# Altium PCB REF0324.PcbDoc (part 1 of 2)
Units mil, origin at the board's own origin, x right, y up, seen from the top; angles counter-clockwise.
Board outline 2010 x 1686 mil, 4 copper layers (Top Layer, Signal Layer 1, Signal Layer 2, Bottom Layer), stack 61.2 mil thick; 109 components, 70 nets, 426 pads, 300 vias.
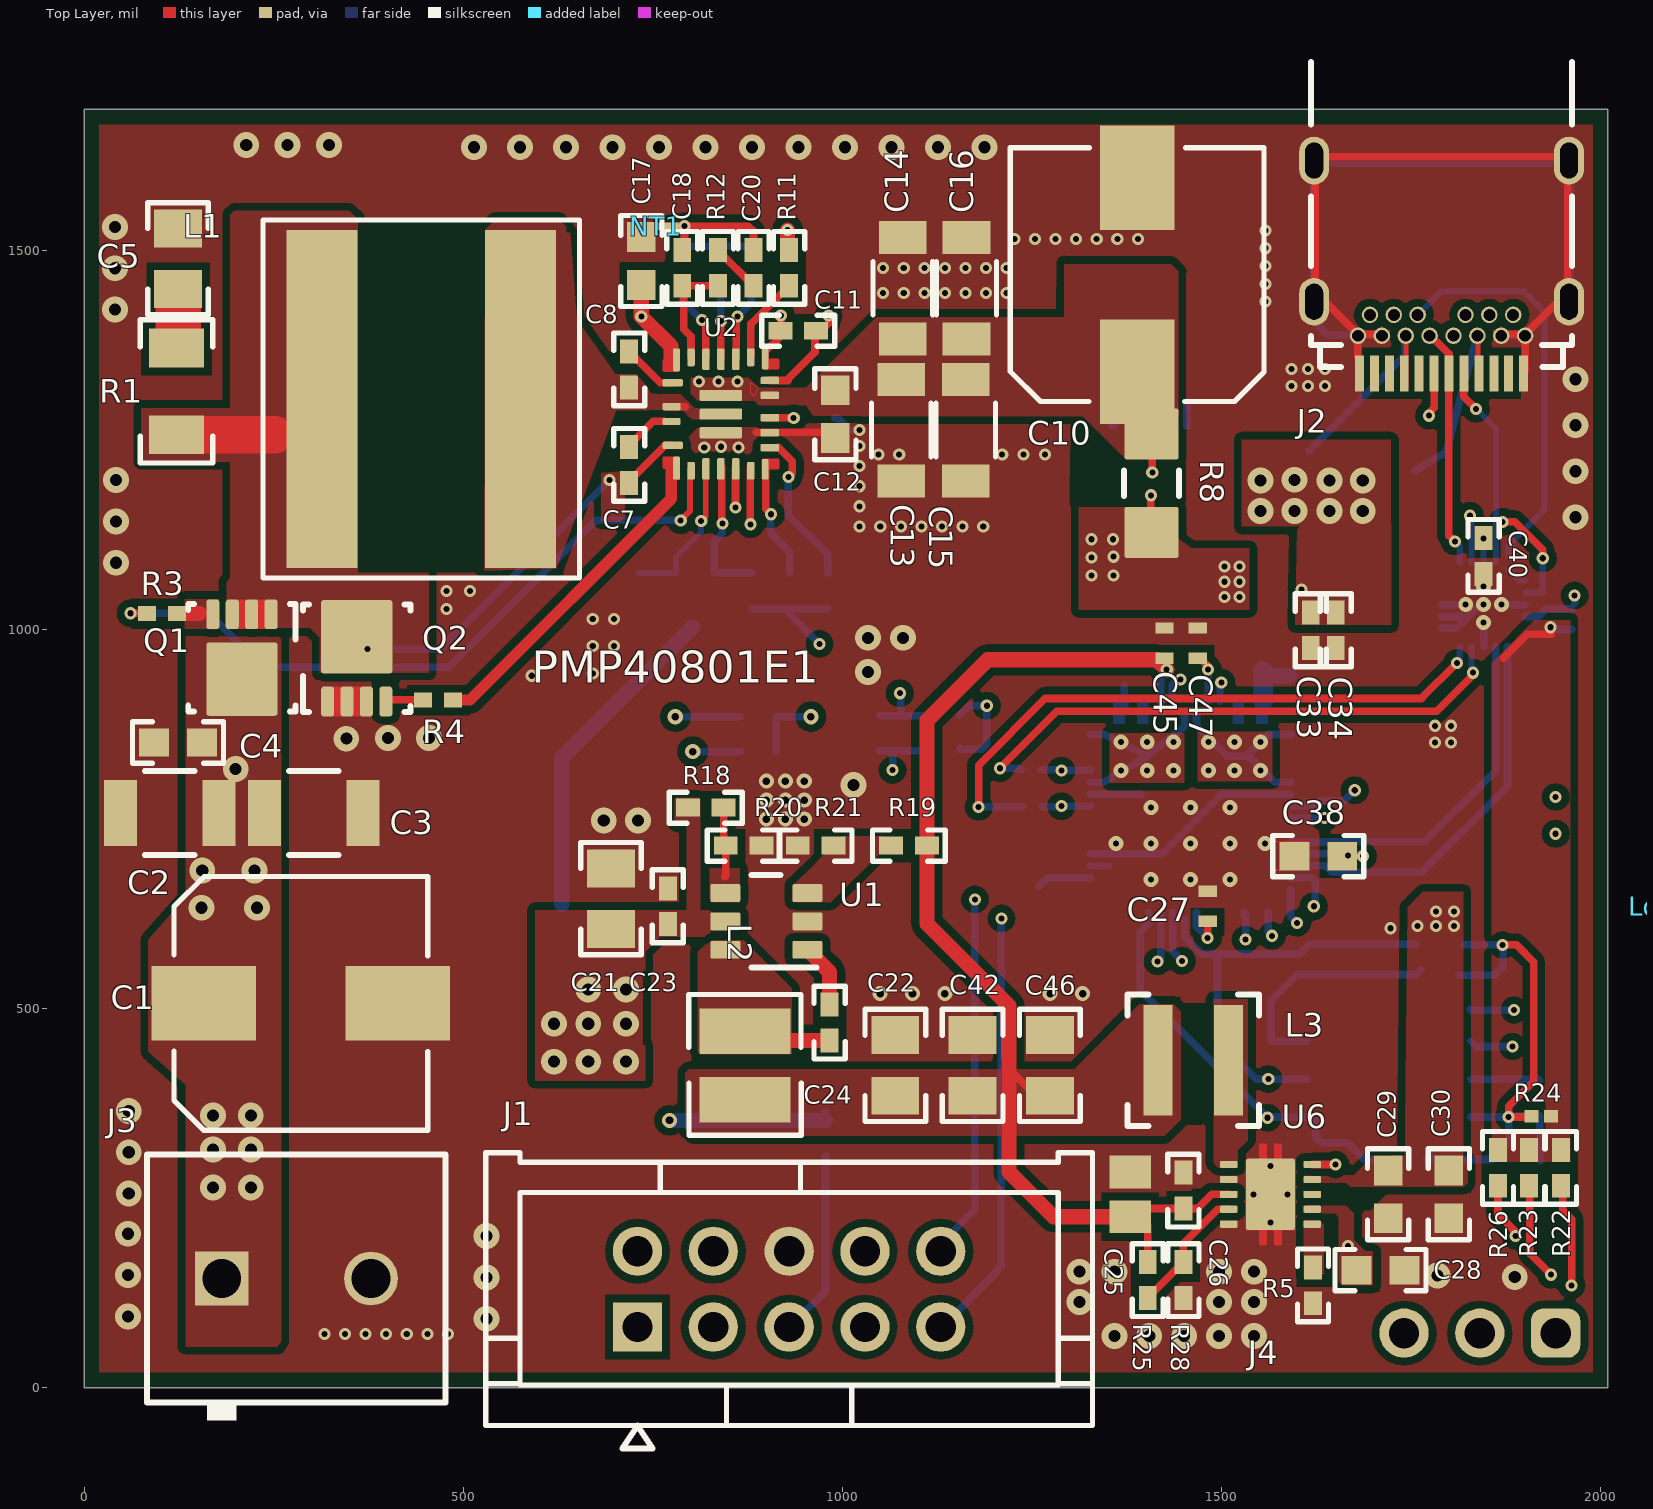
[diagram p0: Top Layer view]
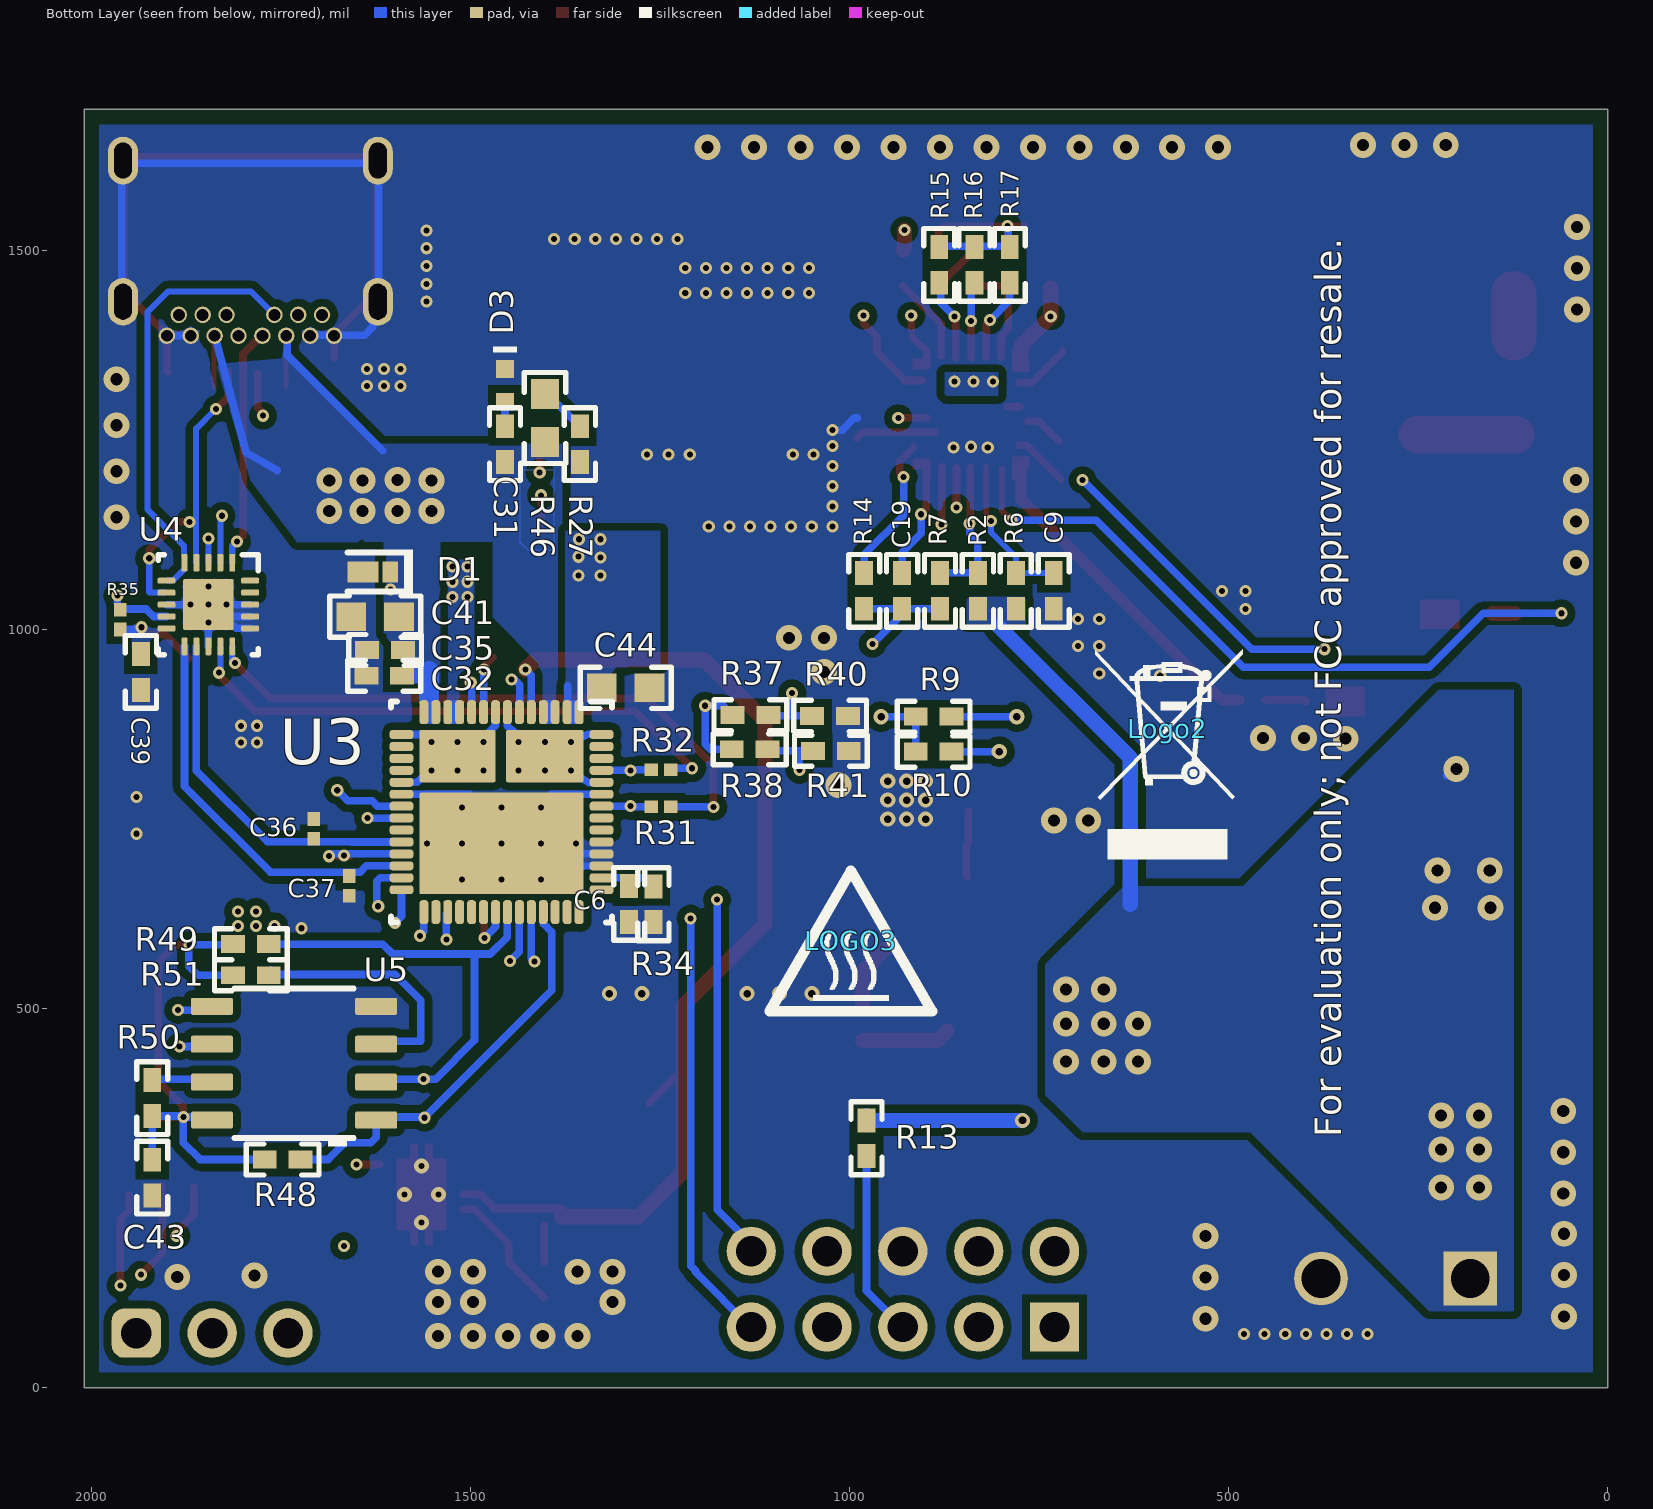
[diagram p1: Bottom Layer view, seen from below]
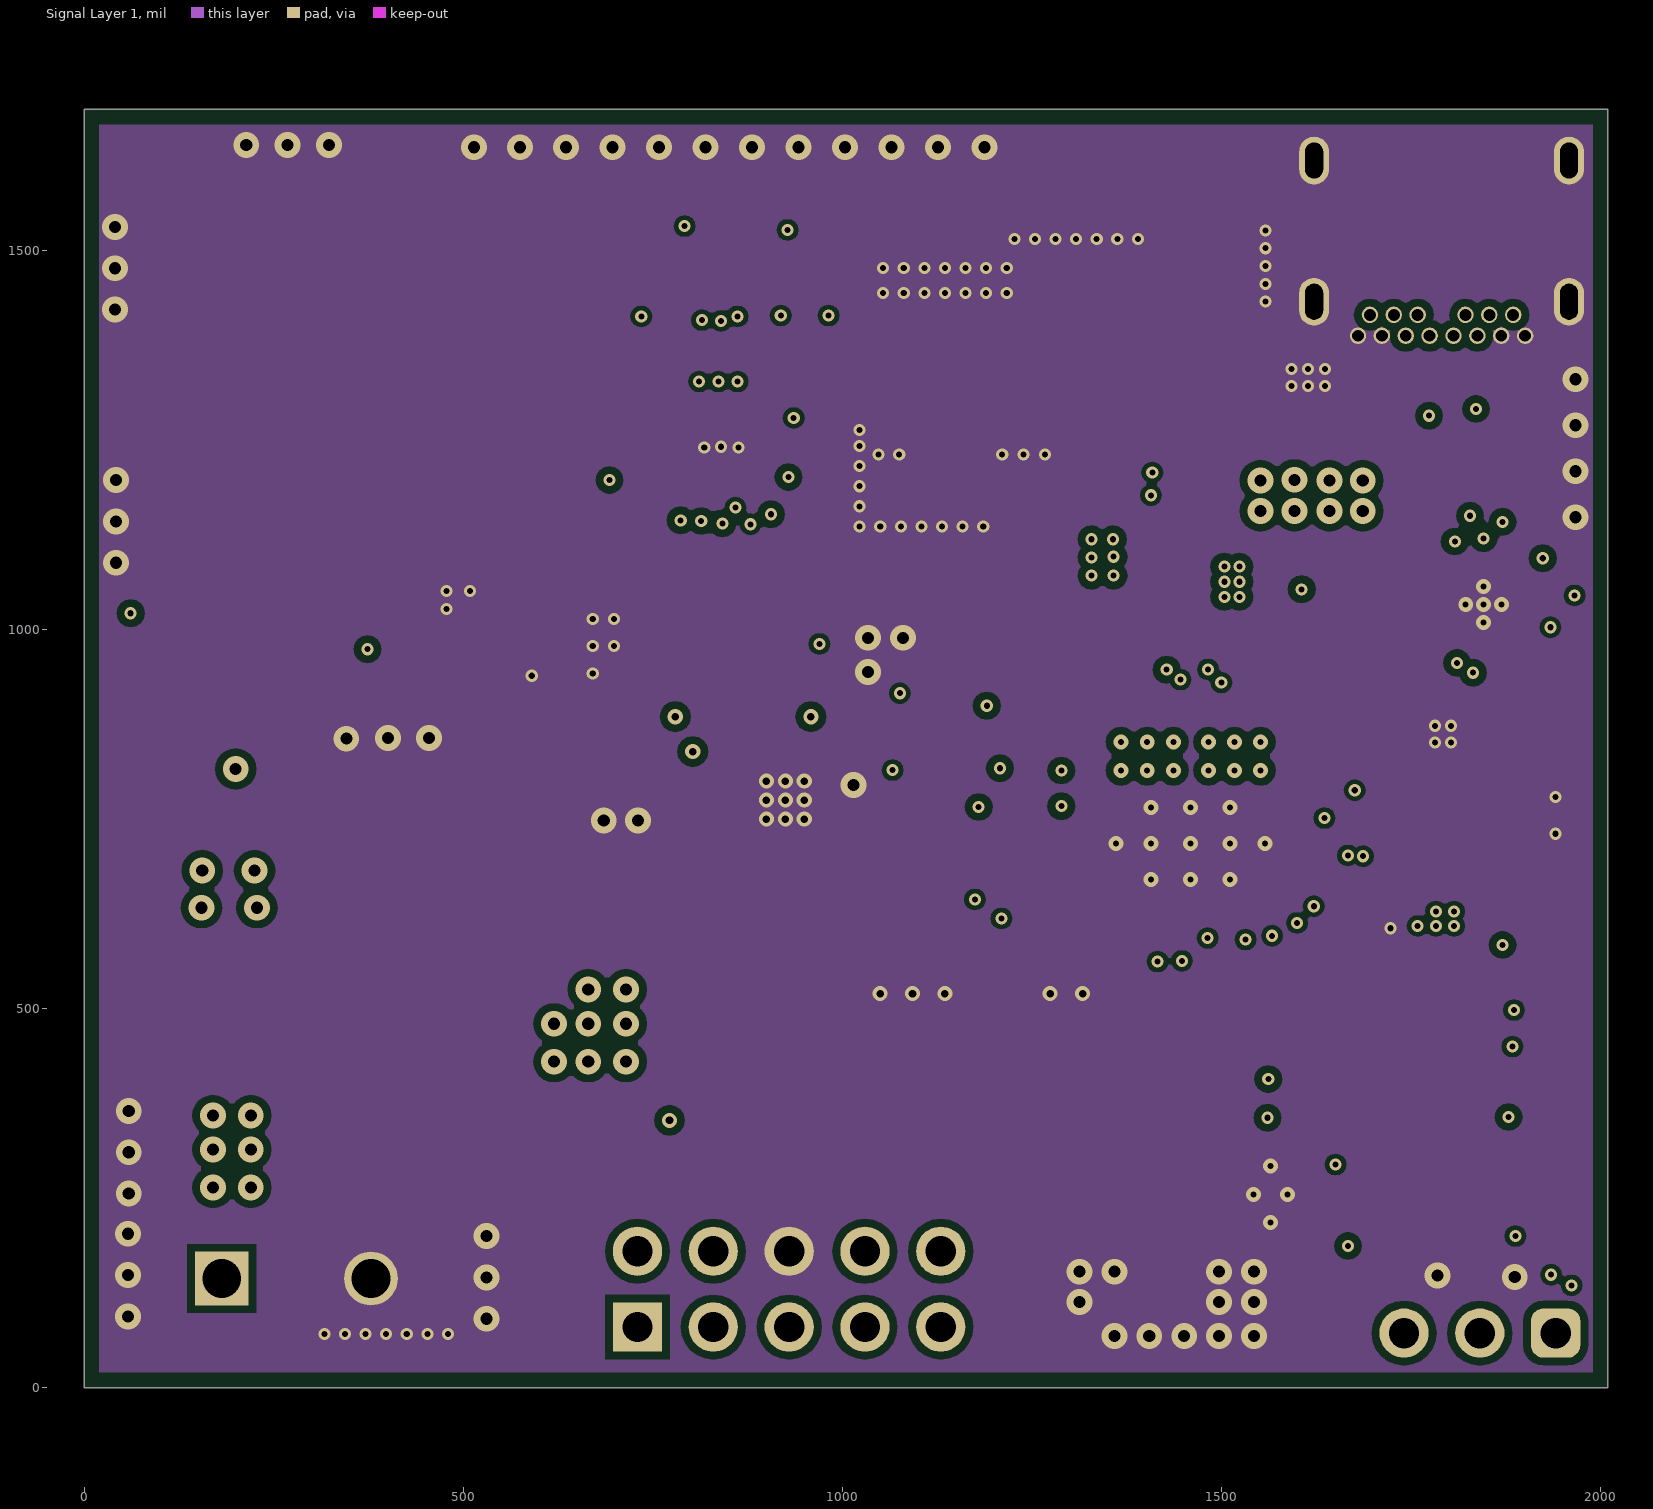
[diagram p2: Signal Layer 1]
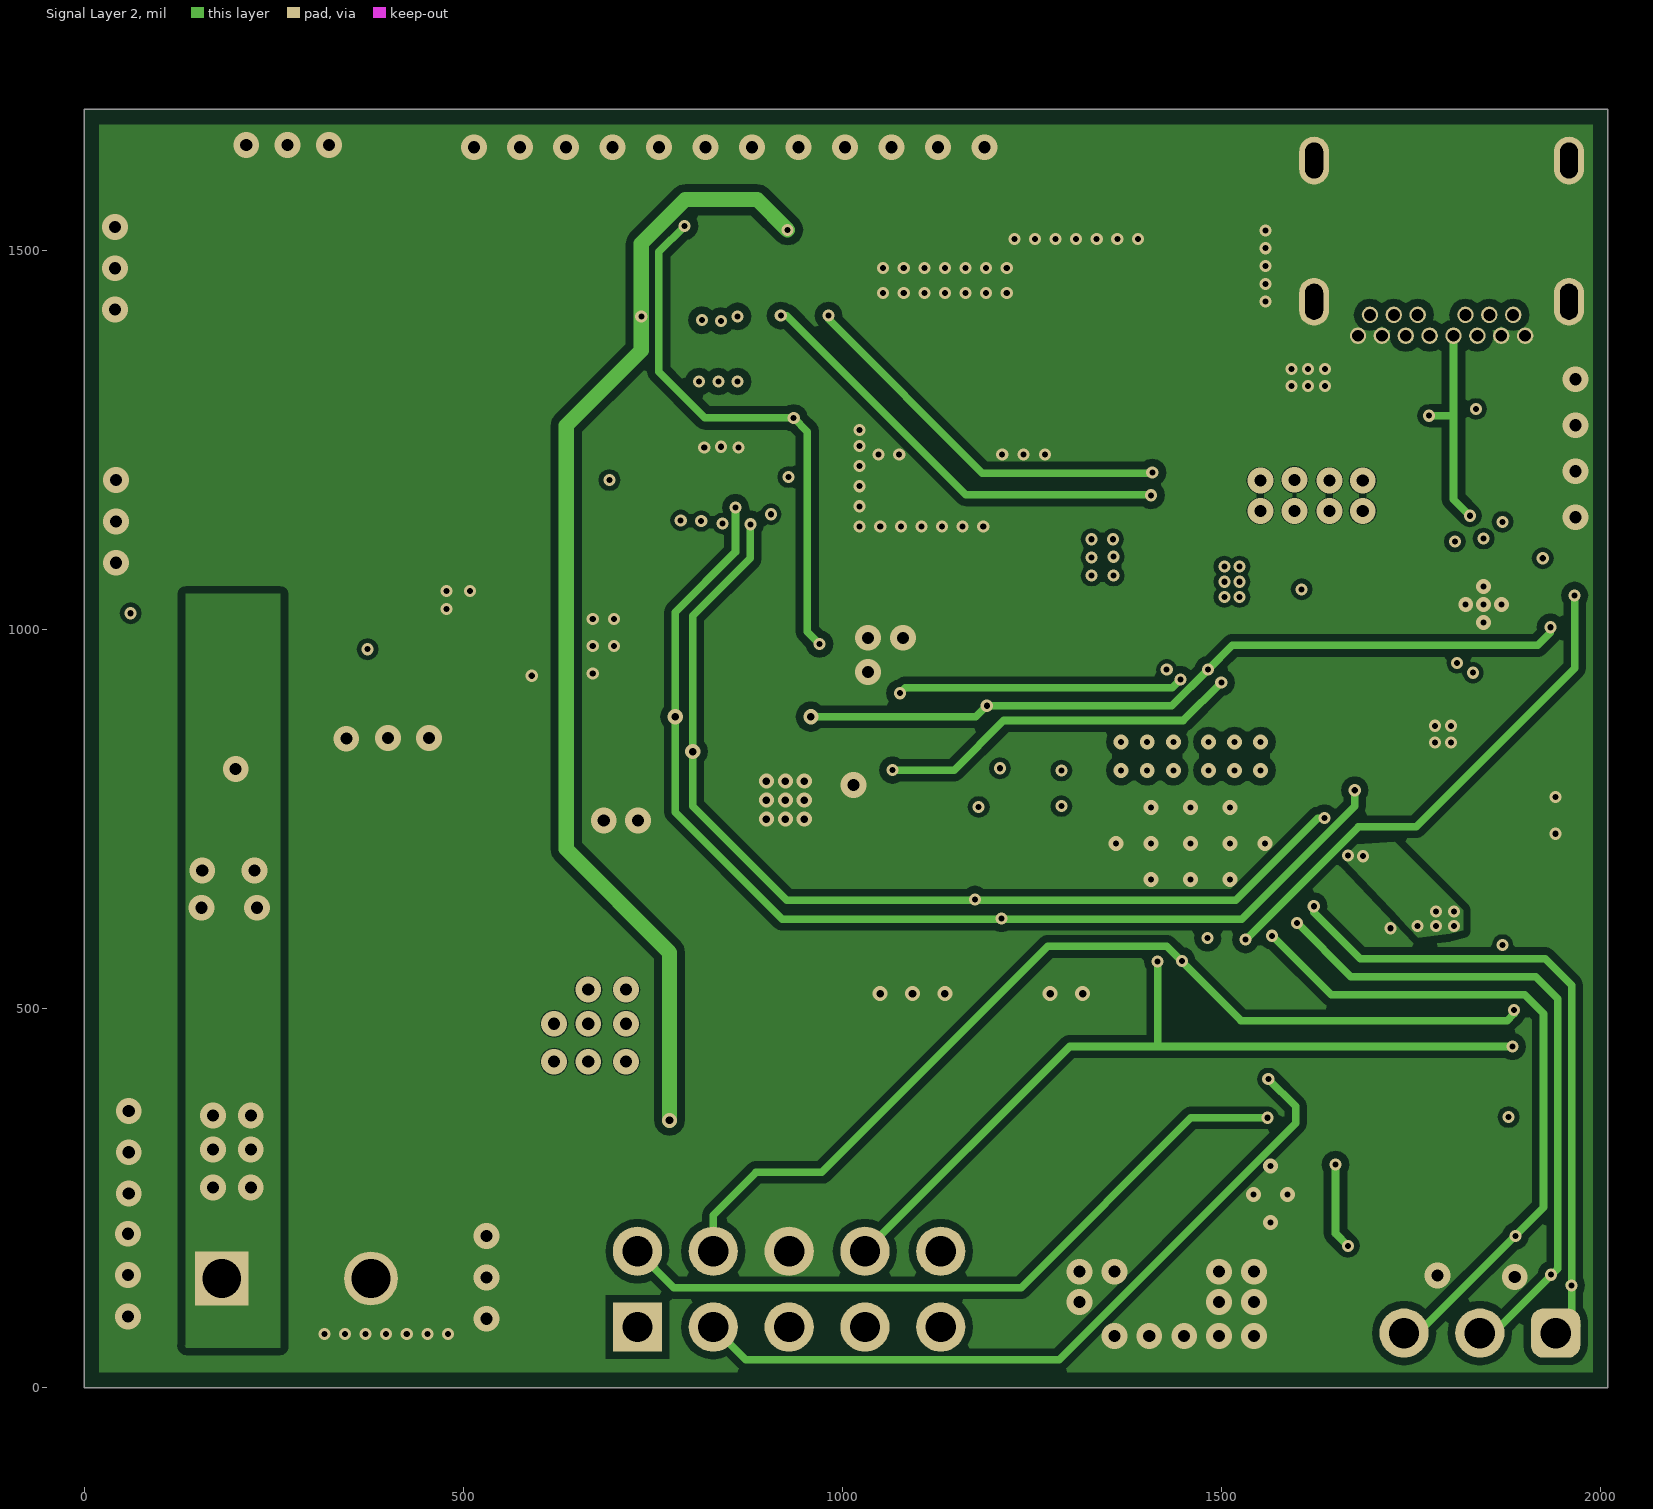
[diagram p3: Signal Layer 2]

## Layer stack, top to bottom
Top Solder: solder mask 0.4, Solder Resist, Dk 3.5
Top Layer: signal copper 2.8
Dielectric 1: core 7, FR-4, Dk 4.2
Signal Layer 1: signal copper 2.8
Dielectric 2: prepreg 36, FR-4, Dk 4.2
Signal Layer 2: signal copper 2.8
Dielectric3: core 7, FR-4, Dk 4.2
Bottom Layer: signal copper 2.8
Bottom Solder: solder mask 0.4, Solder Resist, Dk 3.5

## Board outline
0,0 0,1686 2010,1686 2010,0

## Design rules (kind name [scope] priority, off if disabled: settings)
AcuteAngle [All] p1: minimum=4.50000000000000E+0001 checktracksonly=FALSE
AssemblyTestPointUsage [All] p1: valid=2
BoardOutlineClearance BoardOutlineClearance_1 [ispad and InComponent('J3')] p1: gap=20 ignorepadtopadclearanceinfootprint=FALSE
BoardOutlineClearance BoardOutlineClearance_MountingHoles [OnCopper and InComponentClass('Mounting Holes')] p2: gap=20 ignorepadtopadclearanceinfootprint=FALSE
BoardOutlineClearance BoardOutlineClearance_Poly [OnCopper and IsPoly] p3: gap=20 ignorepadtopadclearanceinfootprint=FALSE
BoardOutlineClearance [OnCopper and Not InComponentClass('Logo') and not InComponentClass('FiducialMark') and not InRegion(1000,500,4000,800) and not InPoly] p4: gap=20 ignorepadtopadclearanceinfootprint=FALSE
Clearance Clearance_3 [InComponent('NT1')] p1: gap=3 ignorepadtopadclearanceinfootprint=FALSE
Clearance Clearance_2 [isPad or IsArc vs IsKeepOut] p2: gap=10 ignorepadtopadclearanceinfootprint=FALSE
Clearance Clearance_1 [InPolygon AND (INNet(VIN) OR InNet('SW')OR InNet('SENS')OR InNet('VBUS1')OR InNet('VBUS2'))] p3: gap=10 ignorepadtopadclearanceinfootprint=FALSE
Clearance Clearance_Keepouts [((IsTrack Or IsArc) And Not InPoly) And IsFree and IsKeepOut vs ((IsTrack Or IsArc) And Not InPoly) And IsFree and IsKeepOut] p4: gap=10 ignorepadtopadclearanceinfootprint=FALSE
Clearance Clearance_Poly [InPolygon] p5: gap=10 ignorepadtopadclearanceinfootprint=FALSE
Clearance [All] p6: gap=3 ignorepadtopadclearanceinfootprint=FALSE
ComponentClearance ComponentClearance_1 [InComponent('U1') vs InComponent('NT1')] p1: gap=0 collisioncheckmode=3 verticalgap=0 showdistances=FALSE
ComponentClearance ComponentClearance_MountingHoles_FiducialMarks [InComponentClass('Mounting Holes') vs InComponentClass('FiducialMark')] p2: gap=50 collisioncheckmode=3 verticalgap=10 showdistances=FALSE
ComponentClearance ComponentClearance_Shunt [InComponentClass('Header') vs InComponentClass('Shunt')] p3: gap=0 collisioncheckmode=3 verticalgap=0 showdistances=FALSE
ComponentClearance ComponentClearance_Logo [InComponentClass('Logo')] p4: gap=50 collisioncheckmode=3 verticalgap=10 showdistances=FALSE
ComponentClearance ComponentClearance_ScrewToNut [(HasFootprint('NY PMS 440 0025 PH')) vs (HasFootprint('Keystone_1902C'))] p5: gap=5 collisioncheckmode=3 verticalgap=10 showdistances=FALSE
ComponentClearance ComponentClearance_MountingHoles [InComponentClass('Mounting Holes')] p6: gap=250 collisioncheckmode=3 verticalgap=100000 showdistances=FALSE
ComponentClearance ComponentClearance_SmallPassives [HasFootprint('0201*') or HasFootprint('0402*') or HasFootprint('0508') or HasFootprint('0603*') or HasFootprint('0612') or HasFootprint('0805*') or HasFootprint('0815*') or HasFootprint('0830*') or HasFootprint('1206*') or HasFootprint('1210*') or HasFootprint('1808*') or HasFootprint('1812*') or HasFootprint('1825*') or HasFootprint('2010*') or HasFootprint('2220*') or HasFootprint('2225*') or HasFootprint('2512*') or HasFootprint('2728*') or HasFootprint('3518*') vs HasFootprint('0201*') or HasFootprint('0402*') or HasFootprint('0508') or HasFootprint('0603*') or HasFootprint('0612') or HasFootprint('0805*') or HasFootprint('0815*') or HasFootprint('0830*') or HasFootprint('1206*') or HasFootprint('1210*') or HasFootprint('1808*') or HasFootprint('1812*') or HasFootprint('1825*') or HasFootprint('2010*') or HasFootprint('2220*') or HasFootprint('2225*') or HasFootprint('2512*') or HasFootprint('2728*') or HasFootprint('3518*')] p7: gap=14.96 collisioncheckmode=3 verticalgap=10 showdistances=FALSE
ComponentClearance ComponentClearance_THtoSMT [IsThruComponent vs IsSMTComponent] p8: gap=30 collisioncheckmode=3 verticalgap=30 showdistances=FALSE
ComponentClearance ComponentClearance_THtoTH [IsThruComponent vs IsThruComponent] p9: gap=30 collisioncheckmode=3 verticalgap=30 showdistances=FALSE
ComponentClearance [All] p10 off: gap=30 collisioncheckmode=3 verticalgap=10 showdistances=FALSE
DiffPairsRouting [InDifferentialPairClass('All Differential Pairs')] p1: maxlimit=10 minlimit=5 mostfreqgap=8 toplayer_minwidth=5 toplayer_maxwidth=10 toplayer_prefwidth=8 midlayer1_minwidth=5 midlayer1_maxwidth=10 midlayer1_prefwidth=8 midlayer2_minwidth=5 midlayer2_maxwidth=10 midlayer2_prefwidth=8 bottomlayer_minwidth=5 bottomlayer_maxwidth=10 bottomlayer_prefwidth=8 maxuncoupledlength=10000
FabricationTestPointUsage TestPointUsage [All] p1: valid=2 allowmultiple=FALSE
FabricationTestpoint Testpoint [All] p1: side=3 testpointundercomponent=TRUE minsize=40 maxsize=100 preferedsize=60 minholesize=0 maxholesize=40 preferedholesize=32 testpointgrid=1 allowsidetop=TRUE allowsidebottom=TRUE usegrid=TRUE gridtolerance=0.01
FanoutControl Fanout_LCC [IsLCC] p1: bgadir=Out bgaviamode=Centered fanoutstyle=Auto fanoutdirection=Alternating viagrid=1 // Fanout_LCC (Default Rule)
FanoutControl Fanout_BGA [IsBGA] p2: bgadir=Out bgaviamode=Centered fanoutstyle=Auto fanoutdirection=Alternating viagrid=1 // Fanout_BGA (Default Rule)
FanoutControl Fanout_Default [All] p4: bgadir=Out bgaviamode=Centered fanoutstyle=Auto fanoutdirection=Alternating viagrid=1 // Fanout_Default (Default Rule)
FanoutControl Fanout_Small [(CompPinCount < 5)] p5: bgadir=Out bgaviamode=Centered fanoutstyle=Auto fanoutdirection=OutThenIn viagrid=1 // Fanout_Small (Default Rule)
HoleSize [All] p1: absolutevalues=TRUE maxlimit=251 minlimit=6 maxpercent=80.000 minpercent=20.000
HoleToHoleClearance [All] p1: gap=6 allowstackedmicrovias=TRUE
MinimumAnnularRing MinimumAnnularRing_ThermalPadVias [IsPad] p1: minimumring=2
MinimumAnnularRing [All] p2: minimumring=3
MinimumSolderMaskSliver MinimumSolderMaskSliver_Logo [InComponentClass('Logo') vs InComponentClass('Logo')] p1: minsoldermaskwidth=1
MinimumSolderMaskSliver [All] p2: minsoldermaskwidth=0
PlaneConnect [All] p1: planeconnectstyle=Direct reliefexpansion=10 reliefentries=4 reliefconductorwidth=10 reliefairgap=10
PolygonConnect [All] p1: connectstyle=Direct reliefconductorwidth=10 reliefentries=4 polygonreliefangle="90 Angle" airgapwidth=10
RoutingVias ThermalPadVias [IsVia and InAnyComponent] p1: holewidth=7.87 width=19.68 viastyle="Through Hole" minholewidth=7.8 minwidth=16 maxholewidth=12.99 maxwidth=23.62
RoutingVias [All] p2: holewidth=16 width=34 viastyle="Through Hole" minholewidth=6 minwidth=10 maxholewidth=40 maxwidth=65
ShortCircuit ShortCircuit_1 [ispad and InComponent('U1')] p1: allowed=TRUE
ShortCircuit [All] p2: allowed=FALSE
SilkToSilkClearance SilkToSilkClearance_Pb-FreeLogo [(HasFootprint('Pb-Free_Overlay_Medium') OR HasFootprint('Pb-Free_Overlay_Small')) vs (HasFootprint('Pb-Free_Overlay_Medium') OR HasFootprint('Pb-Free_Overlay_Small'))] p1: silktosilkclearance=0
SilkToSilkClearance [All] p2: silktosilkclearance=0
SilkToSolderMaskClearance [IsPad] p1: minsilkscreentomaskgap=0 clearancetoexposedcopper=TRUE
SilkToSolderMaskClearance SilkToComponentPadClearance [(IsPad or IsFill or IsRegion) and InAnycomponent] p2: minsilkscreentomaskgap=0 clearancetoexposedcopper=TRUE
SolderMaskExpansion [All] p1: expansion=1.97
Width [All] p1: maxlimit=100 minlimit=6 preferedwidth=10 midlayer1_minwidth=7 midlayer2_minwidth=7 bottomlayer_minwidth=7 minimp=50.000000 maximp=50.000000 favimp=50.000000 checkconnectedcopper=TRUE
14 further rules are at their usual default settings.

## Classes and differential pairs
component class Sheet2_PD_Sch: C6 C27 C31 C32 C33 C34 C35 C36 C37 C38 C39 C40 C41 C43 C44 C45 C47 D1 D3 J2 J4 R22 R23 R24 R26 R27 R31 R32 R34 R35 R37 R38 R40 R41 R46 R48 R49 R50 R51 R? U3 U4 U5
component class Sheet1_Power_Sch: C1 C2 C3 C4 C5 C7 C8 C9 C10 C11 C12 C13 C14 C15 C16 C17 C18 C19 C20 C21 C22 C23 C24 C25 C26 C28 C29 C30 C42 C46 J1 J3 L1 L2 L3 Logo1 Logo2 LOGO3 NT1 Q1 Q2 R1 R2 R3 R4 R5 R6 R7 R8 R9 R10 R11 R12 R13 R14 R15 R16 R17 R18 R19 R20 R21 R25 R28 U1 U2 U6
component class Header: J4

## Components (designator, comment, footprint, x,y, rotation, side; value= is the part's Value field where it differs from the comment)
C1 "EEHZA1H680P" SM_RADIAL_8MM 286,507 r0 top value=68uF
C2 "CGA6P1X7R1N106M250AC" 1210_280 113,758 r180 top value=10uF
C3 "CGA6P1X7R1N106M250AC" 1210_280 303,758 r0 top value=10uF
C4 "GRT188R61H105ME13D" 0603 124,851 r180 top value=1uF
C5 "GRM21AR72E222KW01D" 0805_HV 124,1489 r90 top value=2200pF
C6 "GCM155R71H103KA55D" 0402#1 1291,638 r270 bottom value=0.01uF
C7 "CGA2B3X7R1H104K050BB" 0402#1 719,1217 r270 top value=0.1uF
C8 "CGA2B3X7R1H104K050BB" 0402#1 719,1343 r270 top value=0.1uF
C9 "CGA2B3X7R1H103K050BB" 0402#1 731,1051 r270 bottom value=1uF
C10 "EEHZA1E221P" SM_RADIAL_8MM 1389,1468 r90 top value=220uF
C11 "CGA2B3X7R1H104K050BB" 0402#1 942,1394 r180 top value=0.1uF
C12 "GRT188R61H105ME13D" 0603 991,1284 r270 top value=1uF
C13 "CGA5L1X7R1H106K160AC" 1206_190 1078,1263 r270 top value=10uF
C14 "CGA5L1X7R1H106K160AC" 1206_190 1080,1450 r90 top value=10uF
C15 "CGA5L1X7R1H106K160AC" 1206_190 1163,1263 r270 top value=10uF
C16 "CGA5L1X7R1H106K160AC" 1206_190 1164,1450 r90 top value=10uF
C17 "GRT188R61C475KE13D" 0603 735,1486 r90 top value=4.7uF
C18 "CGA2B2C0G1H101J050BA" 0402#1 789,1477 r90 top value=100pF
C19 "CGA2B3X7R1H103K050BB" 0402#1 931,1051 r270 bottom value=0.01uF
C20 "CGA2B2X7R1H472K050BA" 0402#1 883,1477 r90 top value=4700pF
C21 "C2012X7R1V475K125AC" 0805_HV 695,645 r90 top value=4.7uF
C22 "GRM21BD70J226ME44L" 0805_HV 1070,425 r90 top value=22uF
C23 "GCM155R71H104KE02D" 0402#1 770,635 r90 top value=0.1uF
C24 "GCM155R71H104KE02D" 0402#1 983.37,481.64 r270 top value=0.1uF
C25 "GRM21BR60J476ME15L" 0805L 1380,255 r90 top value=47uF
C26 "GCM155R71H104KE02D" 0402#1 1450,260 r90 top value=0.1uF
C27 "CL05A106MP5NUNC" 0402_070 1482,635 r90 top value=10uF
C28 "C1608X5R1A226M080AC" 0603 1710,155 r0 top value=22uF
C29 "C1608X5R1A226M080AC" 0603 1720,255 r270 top value=22uF
C30 "C1608X5R1A226M080AC" 0603 1800,255 r270 top value=22uF
C31 "GRM188R6YA475KE15D" 0603 1402,1279 r90 bottom value=4.7uF
C32 "GCM155R71H103KA55D" 0402#1 1614,939 r0 bottom value=0.01uF
C33 "GCM155R71H103KA55D" 0402#1 1618,999 r270 top value=0.01uF
C34 "GCM155R71H103KA55D" 0402#1 1651,999 r270 top value=0.01uF
C35 "GCM155R71H103KA55D" 0402#1 1613,973 r0 bottom value=0.01uF
C36 "GRM033R71E221KA01D" 0201 1707,737 r90 bottom value=220pF
C37 "GRM033R71E221KA01D" 0201 1660,662 r270 bottom value=220pF
C38 "C1608X5R1A226M080AC" 0603 1628,701 r180 top value=22uF
C39 "EMK105BJ105KVHF" 0402#1 1935,944 r270 bottom value=1uF
C40 "GCM155R71H104KE02D" 0402#1 1846,1097 r270 top value=0.1uF
C41 "GRM188R61E106MA73D" 0603 1626,1017 r0 bottom value=10uF
C42 "GRM21BD70J226ME44L" 0805_HV 1171.97,425 r90 top value=22uF
C43 "885012205037" 0402#1 1920,277 r270 bottom value=0.1uF
C44 "GRM188R61E106MA73D" 0603 1295.62,923.02 r180 bottom value=10uF
C45 "CL05A106MP5NUNC" 0402_070 1469,982 r90 top value=10uF
C46 "GRM21BD70J226ME44L" 0805_HV 1273.94,425 r90 top value=22uF
C47 "CL05A106MP5NUNC" 0402_070 1425,982 r90 top value=10uF
D1 "NSR20F30NXT5G" DSN2_0603 1631.2,1076 r0 bottom value=30V
D3 "LW QH8G-Q2S2-3K5L-1" "LW QH8G_White" 1455,1322 r90 bottom value=White
J1 "5103308-1" CONN_5103308-1 930,130 r0 top
J2 "632723300011" Wurth_632_723_300_011 1790.5,1754.37 r180 top
J3 "691213710002" Wurth_691213710002 280,144 r0 top
J4 "TSW-103-07-G-S" TSW-103-07-G-S 1841,72 r180 top
L1 "XAL1010-472MEB" XAL1010 445,1304 r0 top value=4.7uH
L2 "ME3220-682MLB" ME3220 871.92,425 r270 top value=6.8uH
L3 "78438356022" WE-MAIA_4020 1463,432 r0 top value=2.2uH
Logo1 "FCC disclaimer" FCC_disclaimer 2090,635 r90 top
Logo2 "WEEE logo" WEEE_Minimum 580.9,869.25 r180 bottom
LOGO3 "CAUTION HOT SURFACE" IEC_HotSurface_Small 998.5,589.62 r180 bottom
NT1 "Net-Tie" Net-Tie_10milWide_30milLong 754,1532 r0 top net-tie
Q1 "IPZ40N04S5L4R8ATMA1" PG-TSDSON-8-32 208.33,962.97 r270 top value=40V
Q2 "IPZ40N04S5L4R8ATMA1" PG-TSDSON-8-32 359.67,962.03 r90 top value=40V
R1 "ERJ-8RQF2R2V" 1206 122,1314 r270 top value=2.20
R2 "CRCW0402100KFKED" 0402#1 831,1051 r270 bottom value=147k
R3 "CRCW06031R00FKEA" 0402#2 103,1021 r0 top value=1.00
R4 "CRCW06031R00FKEA" 0402#2 467,907 r180 top value=1.00
R5 "CRCW040232K4FKED" 0402#1 1621,135 r90 top value=32.4k
R6 "CRCW04020000Z0ED" 0402#1 781,1051 r270 bottom value=0
R7 "CRCW0402115KFKED" 0402#1 881,1051 r90 bottom value=115k
R8 "CRF1206-FZ-R010ELF" FP-CRF1206-FZ-R010ELF_1206-MFG 1408,1193 r270 top
R9 "CRCW04022K20FKED" 0402#1 889.38,885 r0 bottom value=2.20k
R10 "CRCW04022K20FKED" 0402#1 889.38,839 r0 bottom value=2.20k
R11 "CRCW0402102KFKED" 0402#1 930,1477 r270 top value=102k
R12 "CRCW040256K2FKED" 0402#1 836,1477 r270 top value=56.2k
R13 "CRCW04022K20FKED" 0402#1 978,329 r90 bottom value=2.20k
R14 "CRCW040249K9FKED" 0402#1 981,1051 r90 bottom value=49.9k
R15 "CRCW04026K19FKED" 0402#1 882,1481 r270 bottom value=6.19k
R16 "CRCW0402150KFKED" 0402#1 835.5,1481 r270 bottom value=150k
R17 "CRCW040220K0FKED" 0402#1 789,1481 r270 bottom value=20.0k
R18 "CRCW0402100KFKED" 0402#1 820,765 r180 top value=402k
R19 "CRCW040251K1FKED" 0402#1 1088,715 r0 top value=51.1k
R20 "CRCW0402100KFKED" 0402#1 870,715 r180 top value=133k
R21 "CRCW040222K1FKED" 0402#1 965,715 r0 top value=22.1k
R22 "CRCW04023K83FKED" 0402#1 1948,290 r90 top value=3.83k
R23 "CRCW04023K83FKED" 0402#1 1906,290 r90 top value=3.83k
R24 "CRCW02010000Z0ED" 0201 1922,358 r180 top value=0
R25 "CRCW0402100KFKED" 0402#1 1403,142 r90 top value=220k
R26 "ERJ-2RKF1002X" 0402#1 1865,290 r90 top value=10.0k
R27 "CRCW04023R48FKED" 0402#1 1356,1244.51 r90 bottom value=3.48
R28 "CRCW0402100KFKED" 0402#1 1450,142 r90 top value=100k
R31 "CRCW02010000Z0ED" 0201 1249,766 r0 bottom value=0
R32 "CRCW02010000Z0ED" 0201 1249,815 r0 bottom value=0
R34 "CRCW0402100KFKED" 0402#1 1259,637.62 r90 bottom value=100k
R35 "RC0201JR-7D100KL" 0201 1962,1013 r270 bottom value=100k
R37 "ERJ-2RKF1002X" 0402#1 1131,887 r0 bottom value=10.0k
R38 "ERJ-2RKF1002X" 0402#1 1132,842 r0 bottom value=10.0k
R40 "CRCW0402100KFKED" 0402#1 1026,886 r0 bottom value=100k
R41 "CRCW0402100KFKED" 0402#1 1025,840 r0 bottom value=100k
R46 "ERJ-2RKF1002X" 0402#1 1454.75,1244.51 r270 bottom value=10.0k
R48 "CRCW04023K30JNED" 0402#1 1748,301 r0 bottom value=3.3k
R49 "CRCW04023K30JNED" 0402#1 1790,585 r0 bottom value=3.3k
R50 "CRCW04023K30JNED" 0402#1 1920,382 r270 bottom value=3.3k
R51 "CRCW04023K30JNED" 0402#1 1790,544 r0 bottom value=3.3k
U1 "TPS560430YDBVR" DBV0006A_N 900,615 r180 top
U2 "TPS55288dev" RPM0026A 839.96,1284.16 r90 top
U3 "TPS65987DDHRSHR" RSH0056E 1459.38,759.11 r270 bottom
U4 "TPD6S300ARUKR" RUK0020B 1846,1032.88 r270 bottom
U5 "MX25L8006EM1I-12G" SOP-8_150MIL 1733,428 r0 bottom
U6 "TPS2500DRCR" DRC0010J 1564.88,255 r0 top

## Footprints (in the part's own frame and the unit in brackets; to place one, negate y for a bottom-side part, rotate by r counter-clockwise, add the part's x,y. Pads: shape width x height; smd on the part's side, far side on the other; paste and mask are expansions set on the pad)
0201 [mm] "Data from Kemet datasheet CC101_COM dated 7/28/11"
  rect 0.46x0.42 smd mask+0.048: 1(-0.33,0) 2(0.33,0)
  body extent -0.31,-0.16 0.31,0.16, height 0.26
0402#1 [mm] "0402 from SM-752 data"
  rect 0.8x0.6 smd: 1(-0.6,0) 2(0.6,0)
  silkscreen extent -1.22,-0.52 1.22,0.52, body extent -0.55,-0.3 0.55,0.3, height 0.6
0402#2 [mm] "Chip Capacitor, Body 1.0x0.5mm, IPC High Density"
  rect 0.6x0.5 smd: 1(-0.5,0) 2(0.5,0)
  body extent -0.55,-0.3 0.55,0.3, height 1.3
0402_070 [mil] "SMD, 2-Leads, Body 1.2x0.7mm, Height 0.7mm"
  rect 15x24 smd: 1(-20,0) 2(20,0)
  body extent -24,-14 24,14, height 28
0603 [mm] "0603 from SM-752 data"
  rect 1x0.95 smd: 1(-0.8,0) 2(0.8,0)
  silkscreen extent -1.52,-0.69 1.52,0.69, body extent -0.87,-0.47 0.87,0.47, height 1
0805_HV [mil] "0805 with 30mil clearance between pads"
  rect 50x63 smd: 1(-40,0) 2(40,0)
  silkscreen extent -74,-40 74,40, body extent -43,-29 43,29, height 57
0805L [mm] "0805 from SM-752 data"
  rect 1.1x1.4 smd: 1(-0.75,0) 2(0.75,0)
  body extent -1.1,-0.72 1.1,0.72, height 1.45
1206 [mm] "1206 from SM-752 data"
  rect 1.3x1.85 smd: 1(-1.45,0) 2(1.45,0)
  silkscreen extent -2.4,-1.21 2.4,1.21, body extent -1.7,-0.9 1.7,0.9, height 1.35
1206_190 [mm] "1206_190"
  rect 1.1x1.6 smd: 1(-1.7,0) 2(1.7,0)
  silkscreen extent -0.9,-1 0.9,1, body extent -1.75,-0.95 1.75,0.95, height 1.9
1210_280 [mm] "SMD, 2-Leads, Body 3.6x2.8mm, Height 2.8mm"
  rect 1.1x2.2 smd: 1(-1.65,0) 2(1.65,0)
  silkscreen extent -0.84,-1.4 0.84,1.4, body extent -1.8,-1.4 1.8,1.4, height 2.8
CONN_5103308-1 [mm] "TE Connectivity (AMP) Rev E datasheet"
  rect 1.65x1.65 hole 1.016 mask+0: 1(-5.08,-1.27)
  round 1.65 hole 1.016 mask+0: 2(-5.08,1.27) 3(-2.54,-1.27) 4(-2.54,1.27) 5(0,-1.27) 6(0,1.27) 7(2.54,-1.27) 8(2.54,1.27) 9(5.08,-1.27) 10(5.08,1.27)
  silkscreen extent -10.16,-5.33 10.16,4.57, body extent -10.16,-4.57 10.16,4.57, height 9.87
DBV0006A_N [mm] "SOT23, 6-Leads, Body 2.9x1.6mm, Pitch 0.95mm, Lead Span 2.8mm, IPC Medium Density"
  rrect17% 1x0.6 smd: 1(-1.375,0.95) 2(-1.375,0) 3(-1.375,-0.95) 4(1.375,-0.95) 5(1.375,0) 6(1.375,0.95)
  silkscreen extent -1.67,-1.55 0.5,1.55, body extent -1.42,-1.46 1.42,1.46, height 1.12
DRC0010J [mm] "VSON-10"
  rrect42% 0.6x0.24 smd: 1(-1.4,1) 2(-1.4,0.5) 3(-1.4,0) 4(-1.4,-0.5) 5(-1.4,-1) 6(1.4,-1) 7(1.4,-0.5) 8(1.4,0) 9(1.4,0.5) 10(1.4,1)
  rrect12% 1.65x2.4 smd paste-1 mask-2: 11(0,0)
  Top Layer region: -0.375,-1.65 -0.375,-1.2 -0.775,-1.2 -0.794,-1.196 -0.81,-1.185 -0.821,-1.169 -0.825,-1.15 -0.825,-1.15 -0.825,1.15 -0.821,1.169 -0.81,1.185 -0.794,1.196 -0.775,1.2 -0.775,1.2 -0.375,1.2 -0.375,1.65 -0.371,1.669 -0.36,1.685 -0.344,1.696 -0.325,1.7 -0.325,1.7 -0.325,1.7 -0.175,1.7 -0.175,1.7 -0.156,1.696 -0.14,1.685 -0.129,1.669 -0.125,1.65 -0.125,1.65 -0.125,1.2 0.125,1.2 0.125,1.65 0.129,1.669 0.14,1.685 0.156,1.696 0.175,1.7 0.175,1.7 0.175,1.7 0.325,1.7 0.325,1.7 0.344,1.696 0.36,1.685 0.371,1.669 0.375,1.65 0.375,1.65 0.375,1.2 0.775,1.2 0.794,1.196 0.81,1.185 0.821,1.169 0.825,1.15 0.825,1.15 0.825,-1.15 0.821,-1.169 0.81,-1.185 0.794,-1.196 0.775,-1.2 0.775,-1.2 0.375,-1.2 0.375,-1.65 0.371,-1.669 0.36,-1.685 0.344,-1.696 0.325,-1.7 0.325,-1.7 0.175,-1.7 0.156,-1.696 0.14,-1.685 0.129,-1.669 0.125,-1.65 0.125,-1.65 0.125,-1.2 -0.125,-1.2 -0.125,-1.65 -0.129,-1.669 -0.14,-1.685 -0.156,-1.696 -0.175,-1.7 -0.175,-1.7 -0.325,-1.7 -0.344,-1.696 -0.36,-1.685 -0.371,-1.669 -0.375,-1.65
  body extent -1.5,-1.5 1.5,1.5, height 1
DSN2_0603 [mm] "SMD, 2-Leads, Body 1.6x0.8mm"
  rect 0.52x0.7 smd: 1(-0.64,0)
  rect 1.05x0.7 smd: 2(0.275,0)
  silkscreen extent -1.4,-0.75 0.8,0.75, body extent -0.8,-0.4 0.8,0.4, height 0.31
FCC_disclaimer [mil]
FP-CRF1206-FZ-R010ELF_1206-MFG [mm]
  rrect6% 1.7x1.8 smd paste+0 mask+0: 1(-1.65,0) 2(1.65,0)
  silkscreen extent -0.42,-0.93 0.42,0.93, body extent -2.6,-1.02 2.6,1.02, height 0.25
IEC_HotSurface_Small [mil]
  silkscreen extent -107,-93 107,92
"LW QH8G_White" [mm] "SMD, 2-Leads, Body 1x0.5mm"
  rect 0.6x0.6 smd paste-0.3: 1(-0.55,0) 2(0.55,0)
  silkscreen extent 1.1,-0.4 1.3,0.4, body extent -0.55,-0.3 0.55,0.3, height 0.4
ME3220 [mm] "Coilcraft SMT Power Inductor ME3220 inductors"
  rect 1.52x3.05 smd: 1(-1.145,0) 2(1.145,0)
  silkscreen extent -2.38,-1.88 2.34,1.88, body extent -1.75,-1.41 1.75,1.4
Net-Tie_10milWide_30milLong [mil] "10mil net tie, no solder mask opening, no solder paste"
  rect 30x10 smd paste-5 mask-5: 1(-15,0) 2(15,0)
PG-TSDSON-8-32 [mm] "SMD, 8-Leads, Body 3.3x3.3mm"
  rrect45% 1x0.44 smd paste-1 mask-0.05: 1(-1.45,0.975) 2(-1.45,0.325) 3(-1.45,-0.325) 4(-1.45,-0.975) 5(1.45,-0.975) 6(1.45,-0.325) 7(1.45,0.325) 8(1.45,0.975)
  rrect6% 1.71x2.29 on Top Solder: 9(0.395,0)
  rrect8% 2.46x2.39 smd paste-2 mask-2: 9(0.72,0)
  rrect42% 0.3x0.24 on Top Paste: ""(-1.695,-0.325) ""(-1.695,0.325) ""(-1.695,0.975)
  rrect42% 0.7x0.24 on Top Paste: ""(-1.5,-0.975)
  rrect29% 0.35x0.67 on Top Paste: ""(-1.225,0.76) ""(-1.22,-0.11)
  rrect42% 1.4x0.24 on Top Paste: ""(0.35,0.975) ""(0.35,-0.975)
  rrect9% 1.4x1.09 on Top Paste: ""(0.35,0)
  rrect42% 0.6x0.24 on Top Paste: ""(1.55,0.975) ""(1.55,-0.325) ""(1.55,0.325) ""(1.55,-0.975)
  Top Layer region: -1.95,-0.325 -0.95,-0.325 -0.95,1 -1.95,1
  silkscreen extent -1.8,-1.8 1.8,1.8, body extent -1.7,-1.7 1.7,1.7, height 1.15
RPM0026A [mm] "VQFN-HR-26"
  rrect44% 0.775x0.225 smd: 1(-1.812,1.487) 19(1.812,1.487)
  rrect40% 0.6x0.25 smd: 2(-1.9,1) 6(-1.9,-1) 14(1.9,-1) 18(1.9,1)
  rrect40% 0.725x0.25 smd: 3(-1.837,0.5) 4(-1.837,0) 5(-1.837,-0.5) 15(1.837,-0.5) 16(1.837,0) 17(1.837,0.5)
  rrect44% 0.7x0.225 smd: 7(-1.85,-1.488) 13(1.85,-1.488)
  rrect40% 0.25x0.625 smd: 8(-1.125,-1.637) 9(-0.625,-1.637) 10(-0.125,-1.637) 11(0.625,-1.637) 12(1.125,-1.637)
  rrect40% 0.25x0.675 smd: 20(1.05,1.612) 23(-1.05,1.612)
  rrect40% 0.25x0.6 smd: 21(0.25,1.65) 22(-0.25,1.65)
  rrect27% 0.375x1.425 smd: 24(-0.625,0) 25(0,0) 26(0.625,0)
  Top Layer region: -2.15,-1.6 -2.169,-1.596 -2.185,-1.585 -2.196,-1.569 -2.2,-1.55 -2.2,-1.55 -2.2,-1.425 -2.196,-1.406 -2.185,-1.39 -2.169,-1.379 -2.15,-1.375 -2.15,-1.375 -1.55,-1.375 -1.531,-1.379 -1.515,-1.39 -1.504,-1.406 -1.5,-1.425 -1.5,-1.425 -1.5,-1.9 -1.504,-1.919 -1.515,-1.935 -1.531,-1.946 -1.55,-1.95 -1.55,-1.95 -1.8,-1.95 -1.819,-1.946 -1.835,-1.935 -1.846,-1.919 -1.85,-1.9 -1.85,-1.9 -1.85,-1.6
  Top Layer region: 1.5,-1.9 1.504,-1.919 1.515,-1.935 1.531,-1.946 1.55,-1.95 1.55,-1.95 1.8,-1.95 1.819,-1.946 1.835,-1.935 1.846,-1.919 1.85,-1.9 1.85,-1.9 1.85,-1.6 2.15,-1.6 2.169,-1.596 2.185,-1.585 2.196,-1.569 2.2,-1.55 2.2,-1.55 2.2,-1.425 2.196,-1.406 2.185,-1.39 2.169,-1.379 2.15,-1.375 2.15,-1.375 1.55,-1.375 1.531,-1.379 1.515,-1.39 1.504,-1.406 1.5,-1.425 1.5,-1.425
  Top Layer region: 1.425,1.425 1.429,1.406 1.44,1.39 1.456,1.379 1.475,1.375 1.475,1.375 2.15,1.375 2.169,1.379 2.185,1.39 2.196,1.406 2.2,1.425 2.2,1.425 2.2,1.55 2.196,1.569 2.185,1.585 2.169,1.596 2.15,1.6 2.15,1.6 1.825,1.6 1.825,1.9 1.821,1.919 1.81,1.935 1.794,1.946 1.775,1.95 1.775,1.95 1.475,1.95 1.456,1.946 1.44,1.935 1.429,1.919 1.425,1.9 1.425,1.9
  Top Layer region: -2.15,1.375 -2.169,1.379 -2.185,1.39 -2.196,1.406 -2.2,1.425 -2.2,1.425 -2.2,1.55 -2.193,1.575 -2.175,1.593 -2.15,1.6 -2.15,1.6 -1.825,1.6 -1.825,1.9 -1.821,1.919 -1.81,1.935 -1.794,1.946 -1.775,1.95 -1.775,1.95 -1.475,1.95 -1.456,1.946 -1.44,1.935 -1.429,1.919 -1.425,1.9 -1.425,1.9 -1.425,1.425 -1.429,1.406 -1.44,1.39 -1.456,1.379 -1.475,1.375 -1.475,1.375
  body extent -2,-1.75 2,1.75, height 1
RSH0056E [mm] "SMD, 56-Leads, Body 7x7mm, Pitch 0.4mm"
  rrect67% 0.8x0.3 smd paste-0.05 mask-0.05: 1(-3.35,2.6) 2(-3.35,2.2) 3(-3.35,1.8) 4(-3.35,1.4) 5(-3.35,1) 6(-3.35,0.6) 7(-3.35,0.2) 8(-3.35,-0.2) 9(-3.35,-0.6) 10(-3.35,-1) 11(-3.35,-1.4) 12(-3.35,-1.8) 13(-3.35,-2.2) 14(-3.35,-2.6) 29(3.35,-2.6) 30(3.35,-2.2) 31(3.35,-1.8) 32(3.35,-1.4) 33(3.35,-1) 34(3.35,-0.6) 35(3.35,-0.2) 36(3.35,0.2) 37(3.35,0.6) 38(3.35,1) 39(3.35,1.4) 40(3.35,1.8) 41(3.35,2.2) 42(3.35,2.6)
  rrect67% 0.3x0.8 smd paste-0.05 mask-0.05: 15(-2.6,-3.35) 16(-2.2,-3.35) 17(-1.8,-3.35) 18(-1.4,-3.35) 19(-1,-3.35) 20(-0.6,-3.35) 21(-0.2,-3.35) 22(0.2,-3.35) 23(0.6,-3.35) 24(1,-3.35) 25(1.4,-3.35) 26(1.8,-3.35) 27(2.2,-3.35) 28(2.6,-3.35) 43(2.6,3.35) 44(2.2,3.35) 45(1.8,3.35) 46(1.4,3.35) 47(1,3.35) 48(0.6,3.35) 49(0.2,3.35) 50(-0.2,3.35) 51(-0.6,3.35) 52(-1,3.35) 53(-1.4,3.35) 54(-1.8,3.35) 55(-2.2,3.35) 56(-2.6,3.35)
  rrect16% 1.47x1.15 on Bottom Paste: 57(-1.875,0.775) 57(-1.875,2.125) 58(-1.875,-2.15) 58(-1.875,-0.8)
  rrect6% 1.75x2.6 smd paste-2.2: 57(-1.875,1.45)
  rrect6% 1.75x2.55 smd paste-2.2: 58(-1.875,-1.475)
  rrect12% 1.47x1.12 on Bottom Paste: 59(0.215,-1.98) 59(0.215,-0.66) 59(0.215,0.66) 59(0.215,1.98) 59(1.885,-1.98) 59(1.885,-0.66) 59(1.885,0.66) 59(1.885,1.98)
  rrect3% 3.4x5.5 smd paste-2.2: 59(1.05,0)
  Top Layer region: -3.75,-2.2 -2.95,-2.2 -2.95,-2.6 -3.75,-2.6
  Top Layer region: -3.75,-1.4 -2.95,-1.4 -2.95,-1.8 -3.75,-1.8
  Top Layer region: -3.75,1.8 -2.95,1.8 -2.95,1.4 -3.75,1.4
  Top Layer region: -3.75,2.6 -2.95,2.6 -2.95,2.2 -3.75,2.2
  silkscreen extent -3.7,-3.7 3.7,3.7, body extent -3.57,-3.57 3.57,3.57, height 1.01
RUK0020B [mm]
  rrect50% 0.6x0.2 smd: 1(-1.4,0.8) 2(-1.4,0.4) 3(-1.4,0) 4(-1.4,-0.4) 5(-1.4,-0.8) 11(1.4,-0.8) 12(1.4,-0.4) 13(1.4,0) 14(1.4,0.4) 15(1.4,0.8)
  rrect50% 0.2x0.6 smd: 6(-0.8,-1.4) 7(-0.4,-1.4) 8(0,-1.4) 9(0.4,-1.4) 10(0.8,-1.4) 16(0.8,1.4) 17(0.4,1.4) 18(0,1.4) 19(-0.4,1.4) 20(-0.8,1.4)
  rrect13% 0.75x0.75 on Bottom Paste: 21(-0.475,-0.475) 21(-0.475,0.475) 21(0.475,-0.475) 21(0.475,0.475)
  rrect6% 1.7x1.7 smd paste-0.85: 21(0,0)
  silkscreen extent -1.68,-1.68 1.67,1.67, body extent -1.5,-1.5 1.5,1.5, height 0.8
SM_RADIAL_8MM [mm] "Nichicon 8x10"
  rect 3.5x2.5 smd: 1(-3.25,0) 2(3.25,0)
  silkscreen extent -4.25,-4.25 4.25,4.25, body extent -4.25,-4.25 4.25,4.25, height 10.5
SOP-8_150MIL [mm] "SOP, 8-Leads, Body 5.03x4mm, Pitch 1.27mm"
  rrect18% 1.4x0.57 smd: 1(-2.75,1.905) 2(-2.75,0.635) 3(-2.75,-0.635) 4(-2.75,-1.905) 5(2.75,-1.905) 6(2.75,-0.635) 7(2.75,0.635) 8(2.75,1.905)
  silkscreen extent -2,-2.5 2,2.79, body extent -2,-2.5 2,2.5, height 1.76
TSW-103-07-G-S [mm] "Samtec 100mil, 1x3, 230 mil above insulator"
  rrect50% 1.65x1.65 hole 1.016: 1(-2.54,0)
  round 1.65 hole 1.016: 2(0,0) 3(2.54,0)
  body extent -3.81,-1.27 3.81,1.27, height 8.38
WE-MAIA_4020 [mm] "SMD, 2-Leads, Body 4.1x4.1mm"
  rect 0.98x3.7 smd: 1(-1.185,0) 2(1.185,0)
  silkscreen extent -2.2,-2.2 2.2,2.2, body extent -2.05,-2.05 2.05,2.05, height 2.1
WEEE_Minimum [mil] "WEEElie bin"
  silkscreen extent -95,-172 99,104
Wurth_632_723_300_011 [mm] "Connector, Receptacle, USB Type C, R/A"
  rect 0.3x1.2 smd: A1(-2.75,10.58) A2(-2.25,10.58) A3(-1.75,10.58) A4(-1.25,10.58) A5(-0.75,10.58) A6(-0.25,10.58) A7(0.25,10.58) A8(0.75,10.58) A9(1.25,10.58) A10(1.75,10.58) A11(2.25,10.58) A12(2.75,10.58)
  round 0.55 hole 0.4: B1(2.8,9.32) B2(2.4,8.62) B3(1.6,8.62) B4(1.2,9.32) B5(0.8,8.62) B6(0.4,9.32) B7(-0.4,9.32) B8(-0.8,8.62) B9(-1.2,9.32) B10(-1.6,8.62) B11(-2.4,8.62) B12(-2.8,9.32) M1(2,9.32) M2(-2,9.32)
  rrect100% 1x1.6 hole 0.6 slot 1.2 at 90 deg: S1(-4.27,8.18) S2(-4.27,3.45) S3(4.27,3.45) S4(4.27,8.18)
  silkscreen extent -4.37,0.15 4.37,10.36, body extent -4.37,-0.96 4.37,10.83, height 3.07
Wurth_691213710002 [mm] "TH, 2-Leads, Body 10x8.3mm, Pitch 5mm"
  rect 1.8x1.8 hole 1.3: 1(-2.5,0)
  round 1.8 hole 1.3: 2(2.5,0)
  silkscreen extent -5,-4.75 5,4.15, body extent -5.6,-4.15 5,4.15, height 10
XAL1010 [mm] "COILCRAFT"
  rect 2.38x11.31 smd: 1(-3.325,0) 2(3.325,0)
  silkscreen extent -5.3,-6 5.3,6, body extent -5.25,-5.9 5.25,5.9, height 10

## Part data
C1: library part CMP-0012579-3, "CAP, Polymer Hybrid, 68 uF, 50 V, +/- 20%, 30 ohm, 8x10 SMD", Manufacturer=Panasonic, Supplier Part Number 1=P15445CT-ND, Tolerance_%=20%, Value1="30 ohm", Value2=50V, ValueDisplayed=68uF
C2 C3: library part CMP-0085951-1, "CAP, CERM, 10 µF, 75 V,+/- 20%, X7R, AEC-Q200 Grade 1, 1210", Cap_Case=1210, Manufacturer=TDK, TempCo=X7R, Tolerance_%=20%, Value2=75V, ValueDisplayed=10µF
C4 C12: library part CMP-0081784-1, "CAP, CERM, 1 µF, 50 V,+/- 20%, X5R, AEC-Q200 Grade 3, 0603", Cap_Case=0603, Manufacturer=MuRata, Supplier Part Number 1=490-12331-1-ND, TempCo=X5R, Tolerance_%=20%, Value2=50V, ValueDisplayed=1µF
C5: library part CMP-0008253-2, "CAP, CERM, 2200 pF, 250 V, +/- 10%, X7R, 0805", Cap_Case=0805, Manufacturer=MuRata, Supplier Part Number 1=490-3529-1-ND, TempCo=X7R, Tolerance_%=10%, Value1=Unknown, Value2=250V, ValueDisplayed=2200pF
C6 C32 C33 C34 C35: library part CMP-0006355-2, "CAP, CERM, 0.01 uF, 50 V, +/- 10%, C0G/NP0, 0402", Cap_Case=0402, Manufacturer=MuRata, Supplier Part Number 1=490-4762-1-ND, TempCo=C0G/NP0, Tolerance_%=10%, Value1=Unknown, Value2=50V, ValueDisplayed=0.01uF
C7 C8 C11: library part CMP-0006325-2, "CAP, CERM, 0.1 uF, 50 V, +/- 10%, X7R, AEC-Q200 Grade 1, 0402", Cap_Case=0402, Manufacturer=TDK, Supplier Part Number 1=445-6899-1-ND, TempCo=X7R, Tolerance_%=10%, Value1="0.039064 ohm", Value2=50V, ValueDisplayed=0.1uF
C9: library part CMP-0006324-2, "CAP, CERM, 1 uF, 50 V, +/- 10%, X7R, AEC-Q200 Grade 1, 0402", Cap_Case=0402, Manufacturer=TDK, Supplier Part Number 1=445-6893-1-ND, TempCo=X7R, Tolerance_%=10%, Value1="0.333065 ohm", Value2=50V, ValueDisplayed=1uF
C10: library part CMP-0012571-3, "CAP, Polymer Hybrid, 220 uF, 25 V, +/- 20%, 27 ohm, 8x10 SMD", Manufacturer=Panasonic, Supplier Part Number 1=P15437CT-ND, Tolerance_%=20%, Value1="27 ohm", Value2=25V, ValueDisplayed=220uF
C13 C14 C15 C16: library part CMP-0085950-1, "CAP, CERM, 10 µF, 50 V,+/- 10%, X7R, AEC-Q200 Grade 1, 1206", Cap_Case=1206, Manufacturer=TDK, TempCo=X7R, Tolerance_%=10%, Value2=50V, ValueDisplayed=10µF
C17: library part CMP-0081052-1, "CAP, CERM, 4.7 µF, 16 V,+/- 10%, X5R, AEC-Q200 Grade 3, 0603", Cap_Case=0603, Manufacturer=MuRata, Supplier Part Number 1=490-12319-1-ND, TempCo=X5R, Tolerance_%=10%, Value2=16V, ValueDisplayed=4.7µF
C18: library part CMP-0006308-2, "CAP, CERM, 100 pF, 50 V, +/- 5%, C0G/NP0, AEC-Q200 Grade 1, 0402", Cap_Case=0402, Manufacturer=TDK, Supplier Part Number 1=445-5596-1-ND, TempCo=C0G/NP0, Tolerance_%=5%, Value1=Unknown, Value2=50V, ValueDisplayed=100pF
C19: library part CMP-0006324-2, "CAP, CERM, 0.01 uF, 50 V, +/- 10%, X7R, AEC-Q200 Grade 1, 0402", Cap_Case=0402, Manufacturer=TDK, Supplier Part Number 1=445-6893-1-ND, TempCo=X7R, Tolerance_%=10%, Value1="0.333065 ohm", Value2=50V, ValueDisplayed=0.01uF
C20: library part CMP-0006321-2, "CAP, CERM, 4700 pF, 50 V, +/- 10%, X7R, AEC-Q200 Grade 1, 0402", Cap_Case=0402, Manufacturer=TDK, Supplier Part Number 1=445-5607-1-ND, TempCo=X7R, Tolerance_%=10%, Value1="0.413508 ohm", Value2=50V, ValueDisplayed=4700pF
C21: library part CMP-0007885-2, "CAP, CERM, 4.7 uF, 35 V, +/- 10%, X7R, 0805", Cap_Case=0805, Manufacturer=TDK, Supplier Part Number 1=445-7555-1-ND, TempCo=X7R, Tolerance_%=10%, Value1="0.002346 ohm", Value2=35V, ValueDisplayed=4.7uF
C22 C42 C46: library part CMP-0008274-1, "CAP, CERM, 22 uF, 6.3 V, +/- 20%, X7T, 0805", Cap_Case=0805, Manufacturer=MuRata, Supplier Part Number 1=GRM21BD70J226ME44L-ND, TempCo=X7T, Tolerance_%=20%, Value1=Unknown, Value2=6.3V, ValueDisplayed=22uF
C23 C24 C26 C40: library part CMP-0006356-2, "CAP, CERM, 0.1 uF, 50 V, +/- 10%, X7R, AEC-Q200 Grade 1, 0402", Cap_Case=0402, Manufacturer=MuRata, Supplier Part Number 1=490-10672-1-ND, TempCo=X7R, Tolerance_%=10%, Value1=Unknown, Value2=50V, ValueDisplayed=0.1uF
C25: library part CMP-0008284-1, "CAP, CERM, 47 uF, 6.3 V, +/- 20%, X5R, 0805", Cap_Case=0805, Manufacturer=MuRata, Supplier Part Number 1=490-9960-1-ND, TempCo=X5R, Tolerance_%=20%, Value1=Unknown, Value2=6.3V, ValueDisplayed=47uF
C27 C45 C47: library part CMP-0006339-4, "CAP, CERM, 10 uF, 10 V, +/- 20%, X5R, 0402", Cap_Case=0402, Manufacturer="Samsung Electro-Mechanics", TempCo=X5R, Tolerance_%=20%, Value1=Unknown, Value2=10V, ValueDisplayed=10uF
C28 C29 C30 C38: library part CMP-0007005-5, "CAP, CERM, 22 uF, 10 V, +/- 20%, X5R, 0603", Cap_Case=0603, Manufacturer=TDK, Supplier Part Number 1=445-9077-1-ND, TempCo=X5R, Tolerance_%=20%, Value1="0.00371 ohm", Value2=10V, ValueDisplayed=22uF
C31: library part CMP-0007357-5, "CAP, CERM, 4.7 uF, 35 V, +/- 10%, X5R, 0603", Cap_Case=0603, Manufacturer=MuRata, Supplier Part Number 1=490-7205-1-ND, TempCo=X5R, Tolerance_%=10%, Value1=Unknown, Value2=35V, ValueDisplayed=4.7uF
C36 C37: library part CMP-0009770-1, "CAP, CERM, 220 pF, 25 V, +/- 10%, X7R, 0201", Cap_Case=0201, Manufacturer=MuRata, Supplier Part Number 1=490-3176-1-ND, TempCo=X7R, Tolerance_%=10%, Value1=Unknown, Value2=25V, ValueDisplayed=220pF
C39: library part CMP-0006347-2, "CAP, CERM, 1 uF, 16 V, +/- 10%, X5R, 0402", Cap_Case=0402, Manufacturer="Taiyo Yuden", Supplier Part Number 1=587-3709-2-ND, TempCo=X5R, Tolerance_%=10%, Value1=Unknown, Value2=16V, ValueDisplayed=1uF
C41 C44: library part CMP-0007344-5, "CAP, CERM, 10 uF, 25 V, +/- 20%, X5R, 0603", Cap_Case=0603, Manufacturer=MuRata, Supplier Part Number 1=490-7202-1-ND, TempCo=X5R, Tolerance_%=20%, Value1=Unknown, Value2=25V, ValueDisplayed=10uF
C43: library part CMP-0006228-2, "CAP, CERM, 0.1 uF, 16 V, +/- 10%, X7R, 0402", Cap_Case=0402, Manufacturer="Wurth Elektronik", Supplier Part Number 1=732-7532-1-ND, TempCo=X7R, Tolerance_%=10%, Value1=Unknown, Value2=16V, ValueDisplayed=0.1uF
D1: library part CMP-0028829-2, "Diode, Schottky, 30 V, 2 A, 2-XFDFN", Manufacturer="ON Semiconductor", Value1=2A, Value2=0.48V
D3: library part CMP-0002919-2, "LED, White, SMD", Color=White, Manufacturer=OSRAM, Value1=W, Value2=2.8V
J1: library part CMP-0054834-2, "Header (shrouded), 100mil, 5x2, Gold, TH", Manufacturer="TE Connectivity", Supplier Part Number 1=A33159-ND
J2: library part CMP-0080891-1, "Connector, Receptacle, USB Type C, R/A", Color=Black, Current_A=3A, Manufacturer="Wurth Elektronik", Supplier Part Number 1=732-9618-1-ND, Voltage_V=5V
J3: library part CMP-0054823-2, "Terminal Block, 2x1, Brass, TH", Color=Green, Manufacturer="Wurth Elektronik", Supplier Part Number 1=732-2038-ND
J4: library part CMP-0075407-2, "Header, 100mil, 3x1, Gold, TH", Color=Black, Current_A=6.3A, Manufacturer=Samtec, Supplier Part Number 1=SAM1029-03-ND, Voltage_V=550V
L1: library part CMP-0060950-1, "Inductor, Shielded, Composite, 4.7 uH, 24 A, 0.01 ohm, SMD", Manufacturer=Coilcraft, Supplier Part Number 1=994-XAL1010-472MEB, Value1="0.01 ohm", Value2=24A, ValueDisplayed=4.7uH
L2: library part CMP-0060543-1, "Inductor, Drum Core, Ferrite, 6.8 uH, 1.1 A, 0.27 ohm, SMD", Manufacturer=Coilcraft, Value1="0.27 ohm", Value2=1.1A, ValueDisplayed=6.8uH
L3: library part CMP-0064366-1, "Inductor, Shielded, Powdered Iron, 2.2 uH, 4.7 A, 0.035 ohm, AEC-Q200 Grade 1, SMD", Manufacturer="Wurth Elektronik", Supplier Part Number 1=732-11314-1-ND, Value1="0.035 ohm", Value2=4.7A, ValueDisplayed=2.2uH
Logo1: library part CMP-0074847-1, "FCC_disclaimer"
Logo2: library part CMP-0074769-1
LOGO3: library part CMP-0074837-1, "IEC 61010-1 Hot Surface Warning"
NT1: library part CMP-0078142-3, "Single point connection between nets.", Manufacturer=N/A
Q1 Q2: library part CMP-0080660-1, "MOSFET, N-CH, 40 V, 40 A, AEC-Q101, SON-8", Alternate Manufacturer=None, Manufacturer="Infineon Technologies", Supplier Part Number 1=IPZ40N04S5L4R8ATMA1CT-ND, Value1="0.0067 ohm", Value2="22 nC"
R1: library part CMP-0017777-3, "RES, 2.20, 1%, 0.25 W, AEC-Q200 Grade 0, 1206", Manufacturer=Panasonic, Power_W=250mW, Supplier Part Number 1=P2.2RCT-ND, TempCo="200 ppm/C", Tolerance_%=1%, Value2=0.25W, Value_Code=2R20, ValueDisplayed=2.20
R2: library part CMP-0025950-3, "RES, 100 k, 1%, 0.063 W, AEC-Q200 Grade 0, 0402", Manufacturer=Vishay-Dale, Power_W=63mW, Supplier Part Number 1=541-100KLCT-ND, TempCo="100 ppm/C", Tolerance_%=1%, Value2=0.063W, Value_Code=147k
R3 R4: library part CMP-0022170-4, "RES, 1.00, 1%, 0.1 W, AEC-Q200 Grade 0, 0603", Manufacturer=Vishay-Dale, Power_W=100mW, Supplier Part Number 1=52K8059, TempCo="100 ppm/C", Tolerance_%=1%, Value2=0.1W, Value_Code=1R00, ValueDisplayed=1.00
R5: library part CMP-0026294-2, "RES, 32.4 k, 1%, 0.063 W, AEC-Q200 Grade 0, 0402", Manufacturer=Vishay-Dale, Power_W=63mW, Supplier Part Number 1=541-32.4KLCT-ND, TempCo="100 ppm/C", Tolerance_%=1%, Value2=0.063W, Value_Code=32k4, ValueDisplayed=32.4k
R6: library part CMP-0026822-3, "RES, 0, 5%, 0.063 W, AEC-Q200 Grade 0, 0402", Manufacturer=Vishay-Dale, Power_W=63mW, Supplier Part Number 1=541-0.0JCT-ND, TempCo="200 ppm/C", Tolerance_%=5%, Value2=0.063W, Value_Code=0000, ValueDisplayed=0
R7: library part CMP-0025971-3, "RES, 115 k, 1%, 0.063 W, AEC-Q200 Grade 0, 0402", Manufacturer=Vishay-Dale, Power_W=63mW, Supplier Part Number 1=541-115KLCT-ND, TempCo="100 ppm/C", Tolerance_%=1%, Value2=0.063W, Value_Code=115k
R8: library part CMP-0086941-2, "10 mOhms ±1% 1W Chip Resistor 1206 (3216 Metric) Automotive AEC-Q200, Current Sense, Moisture Resistant Metal Element", Manufacturer=Bourns, Power_W=1W, TempCo=50ppm/°C, Tolerance_%=1%, ValueDisplayed=10m
R9 R10 R13: library part CMP-0026231-2, "RES, 2.20 k, 1%, 0.063 W, AEC-Q200 Grade 0, 0402", Manufacturer=Vishay-Dale, Power_W=63mW, Supplier Part Number 1=541-2.20KLCT-ND, TempCo="100 ppm/C", Tolerance_%=1%, Value2=0.063W, Value_Code=2k20, ValueDisplayed=2.20k
R11: library part CMP-0025952-3, "RES, 102 k, 1%, 0.063 W, AEC-Q200 Grade 0, 0402", Manufacturer=Vishay-Dale, Power_W=63mW, Supplier Part Number 1=541-102KLCT-ND, TempCo="100 ppm/C", Tolerance_%=1%, Value2=0.063W, Value_Code=102k
R12: library part CMP-0026453-2, "RES, 56.2 k, 1%, 0.063 W, AEC-Q200 Grade 0, 0402", Manufacturer=Vishay-Dale, Power_W=63mW, Supplier Part Number 1=541-56.2KLCT-ND, TempCo="100 ppm/C", Tolerance_%=1%, Value2=0.063W, Value_Code=56k2, ValueDisplayed=56.2k
R14: library part CMP-0026403-2, "RES, 49.9 k, 1%, 0.063 W, AEC-Q200 Grade 0, 0402", Manufacturer=Vishay-Dale, Power_W=63mW, Supplier Part Number 1=541-49.9KLCT-ND, TempCo="100 ppm/C", Tolerance_%=1%, Value2=0.063W, Value_Code=49k9, ValueDisplayed=49.9k
R15: library part CMP-0026513-2, "RES, 6.19 k, 1%, 0.063 W, AEC-Q200 Grade 0, 0402", Manufacturer=Vishay-Dale, Power_W=63mW, Supplier Part Number 1=541-6.19KLCT-ND, TempCo="100 ppm/C", Tolerance_%=1%, Value2=0.063W, Value_Code=6k19, ValueDisplayed=6.19k
R16: library part CMP-0026021-3, "RES, 150 k, 1%, 0.063 W, AEC-Q200 Grade 0, 0402", Manufacturer=Vishay-Dale, Power_W=63mW, Supplier Part Number 1=541-150KLCT-ND, TempCo="100 ppm/C", Tolerance_%=1%, Value2=0.063W, Value_Code=150k
R17: library part CMP-0026162-2, "RES, 20.0 k, 1%, 0.063 W, AEC-Q200 Grade 0, 0402", Manufacturer=Vishay-Dale, Power_W=63mW, Supplier Part Number 1=541-20.0KLCT-ND, TempCo="100 ppm/C", Tolerance_%=1%, Value2=0.063W, Value_Code=20k0, ValueDisplayed=20.0k
R18: library part CMP-0025950-3, "RES, 100 k, 1%, 0.063 W, AEC-Q200 Grade 0, 0402", Manufacturer=Vishay-Dale, Power_W=63mW, Supplier Part Number 1=541-100KLCT-ND, TempCo="100 ppm/C", Tolerance_%=1%, Value2=0.063W, Value_Code=402k
R19: library part CMP-0026437-2, "RES, 51.1 k, 1%, 0.063 W, AEC-Q200 Grade 0, 0402", Manufacturer=Vishay-Dale, Power_W=63mW, Supplier Part Number 1=541-51.1KLCT-ND, TempCo="100 ppm/C", Tolerance_%=1%, Value2=0.063W, Value_Code=51k1, ValueDisplayed=51.1k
